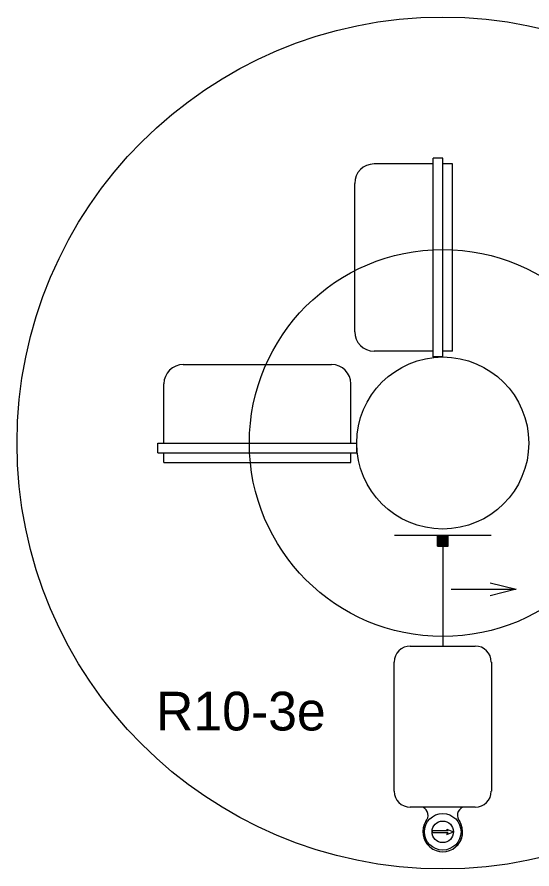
# Model space of a CAD drawing. Extents: x 1695551 to 1695718, y 544410 to 544516.
# Drawn here: x 1695671 to 1695680.98, y 544457.81 to 544474.32 of the extents above; entities that cross this region are included whole.
import ezdxf

# ---------------------------------------------------------------- set-up
doc = ezdxf.new("R2010")
doc.units = 0
doc.layers.add('T_Drafting', color=7, linetype='Continuous')

msp = doc.modelspace()

# ---------------------------------------------------------------- linework, layer by layer
at = {"layer": 'T_Drafting'}
for p, q in [((1695679.065, 544467.733), (1695679.065, 544471.587)), ((1695679.252, 544471.587), (1695679.065, 544471.587)), ((1695679.252, 544467.733), (1695679.252, 544471.587)), ((1695679.065, 544471.473), (1695677.919, 544471.473)), ((1695679.44, 544471.473), (1695679.252, 544471.473)), ((1695679.44, 544467.848), (1695679.44, 544471.473)), ((1695677.544, 544468.223), (1695677.544, 544471.098)), ((1695679.065, 544467.848), (1695677.919, 544467.848)), ((1695679.252, 544467.733), (1695679.065, 544467.733)), ((1695679.44, 544467.848), (1695679.252, 544467.848)), ((1695674.221, 544467.587), (1695677.096, 544467.587)), ((1695673.846, 544466.066), (1695673.846, 544467.212)), ((1695677.471, 544466.066), (1695677.471, 544467.212)), ((1695673.731, 544466.066), (1695677.586, 544466.066)), ((1695673.731, 544465.879), (1695673.731, 544466.066)), ((1695677.586, 544465.879), (1695677.586, 544466.066)), ((1695673.731, 544465.879), (1695677.586, 544465.879)), ((1695673.846, 544465.691), (1695673.846, 544465.879)), ((1695677.471, 544465.691), (1695677.471, 544465.879)), ((1695673.846, 544465.691), (1695677.471, 544465.691)), ((1695680.19, 544464.275), (1695678.315, 544464.275)), ((1695679.148, 544464.066), (1695679.148, 544464.275)), ((1695679.148, 544464.068), (1695679.355, 544464.275)), ((1695679.148, 544464.071), (1695679.351, 544464.275)), ((1695679.148, 544464.075), (1695679.348, 544464.275)), ((1695679.148, 544464.079), (1695679.344, 544464.275)), ((1695679.148, 544464.082), (1695679.341, 544464.275)), ((1695679.148, 544464.086), (1695679.337, 544464.275)), ((1695679.148, 544464.089), (1695679.334, 544464.275)), ((1695679.148, 544464.093), (1695679.33, 544464.275)), ((1695679.148, 544464.096), (1695679.327, 544464.275)), ((1695679.148, 544464.1), (1695679.323, 544464.275)), ((1695679.148, 544464.103), (1695679.319, 544464.275)), ((1695679.148, 544464.107), (1695679.316, 544464.275)), ((1695679.148, 544464.11), (1695679.312, 544464.275)), ((1695679.148, 544464.114), (1695679.309, 544464.275)), ((1695679.148, 544464.117), (1695679.305, 544464.275)), ((1695679.148, 544464.121), (1695679.302, 544464.275)), ((1695679.148, 544464.125), (1695679.298, 544464.275)), ((1695679.148, 544464.128), (1695679.295, 544464.275)), ((1695679.148, 544464.132), (1695679.291, 544464.275)), ((1695679.148, 544464.135), (1695679.288, 544464.275)), ((1695679.148, 544464.139), (1695679.284, 544464.275)), ((1695679.148, 544464.142), (1695679.281, 544464.275)), ((1695679.148, 544464.146), (1695679.277, 544464.275)), ((1695679.148, 544464.149), (1695679.274, 544464.275)), ((1695679.148, 544464.153), (1695679.27, 544464.275)), ((1695679.148, 544464.156), (1695679.266, 544464.275)), ((1695679.148, 544464.16), (1695679.263, 544464.275)), ((1695679.148, 544464.163), (1695679.259, 544464.275)), ((1695679.148, 544464.167), (1695679.256, 544464.275)), ((1695679.148, 544464.17), (1695679.252, 544464.275)), ((1695679.148, 544464.174), (1695679.249, 544464.275)), ((1695679.148, 544464.178), (1695679.245, 544464.275)), ((1695679.148, 544464.181), (1695679.242, 544464.275)), ((1695679.148, 544464.185), (1695679.238, 544464.275)), ((1695679.148, 544464.188), (1695679.235, 544464.275)), ((1695679.148, 544464.192), (1695679.231, 544464.275)), ((1695679.148, 544464.195), (1695679.228, 544464.275)), ((1695679.148, 544464.199), (1695679.224, 544464.275)), ((1695679.148, 544464.202), (1695679.221, 544464.275)), ((1695679.148, 544464.206), (1695679.217, 544464.275)), ((1695679.148, 544464.209), (1695679.213, 544464.275)), ((1695679.148, 544464.213), (1695679.21, 544464.275)), ((1695679.148, 544464.216), (1695679.206, 544464.275)), ((1695679.148, 544464.22), (1695679.203, 544464.275)), ((1695679.148, 544464.224), (1695679.199, 544464.275)), ((1695679.148, 544464.227), (1695679.196, 544464.275)), ((1695679.148, 544464.231), (1695679.192, 544464.275)), ((1695679.148, 544464.234), (1695679.189, 544464.275)), ((1695679.148, 544464.238), (1695679.185, 544464.275)), ((1695679.148, 544464.241), (1695679.182, 544464.275)), ((1695679.148, 544464.245), (1695679.178, 544464.275)), ((1695679.148, 544464.248), (1695679.175, 544464.275)), ((1695679.148, 544464.252), (1695679.171, 544464.275)), ((1695679.148, 544464.255), (1695679.167, 544464.275)), ((1695679.148, 544464.259), (1695679.164, 544464.275)), ((1695679.148, 544464.262), (1695679.16, 544464.275)), ((1695679.148, 544464.266), (1695679.157, 544464.275)), ((1695679.148, 544464.269), (1695679.153, 544464.275)), ((1695679.148, 544464.273), (1695679.15, 544464.275)), ((1695679.15, 544464.066), (1695679.356, 544464.273)), ((1695679.154, 544464.066), (1695679.356, 544464.269)), ((1695679.157, 544464.066), (1695679.356, 544464.266)), ((1695679.356, 544464.066), (1695679.356, 544464.275)), ((1695679.161, 544464.066), (1695679.356, 544464.262)), ((1695679.164, 544464.066), (1695679.356, 544464.259)), ((1695679.168, 544464.066), (1695679.356, 544464.255)), ((1695679.171, 544464.066), (1695679.356, 544464.252)), ((1695679.175, 544464.066), (1695679.356, 544464.248)), ((1695679.178, 544464.066), (1695679.356, 544464.244)), ((1695679.182, 544464.066), (1695679.356, 544464.241)), ((1695679.185, 544464.066), (1695679.356, 544464.237)), ((1695679.189, 544464.066), (1695679.356, 544464.234)), ((1695679.192, 544464.066), (1695679.356, 544464.23)), ((1695679.196, 544464.066), (1695679.356, 544464.227)), ((1695679.2, 544464.066), (1695679.356, 544464.223)), ((1695679.203, 544464.066), (1695679.356, 544464.22)), ((1695679.207, 544464.066), (1695679.356, 544464.216)), ((1695679.21, 544464.066), (1695679.356, 544464.213)), ((1695679.214, 544464.066), (1695679.356, 544464.209)), ((1695679.217, 544464.066), (1695679.356, 544464.206)), ((1695679.221, 544464.066), (1695679.356, 544464.202)), ((1695679.224, 544464.066), (1695679.356, 544464.198)), ((1695679.228, 544464.066), (1695679.356, 544464.195)), ((1695679.231, 544464.066), (1695679.356, 544464.191)), ((1695679.235, 544464.066), (1695679.356, 544464.188)), ((1695679.238, 544464.066), (1695679.356, 544464.184)), ((1695679.242, 544464.066), (1695679.356, 544464.181)), ((1695679.246, 544464.066), (1695679.356, 544464.177)), ((1695679.249, 544464.066), (1695679.356, 544464.174)), ((1695679.253, 544464.066), (1695679.356, 544464.17)), ((1695679.256, 544464.066), (1695679.356, 544464.167)), ((1695679.26, 544464.066), (1695679.356, 544464.163)), ((1695679.263, 544464.066), (1695679.356, 544464.16)), ((1695679.267, 544464.066), (1695679.356, 544464.156)), ((1695679.27, 544464.066), (1695679.356, 544464.153)), ((1695679.274, 544464.066), (1695679.356, 544464.149)), ((1695679.277, 544464.066), (1695679.356, 544464.145)), ((1695679.281, 544464.066), (1695679.356, 544464.142)), ((1695679.284, 544464.066), (1695679.356, 544464.138)), ((1695679.288, 544464.066), (1695679.356, 544464.135)), ((1695679.291, 544464.066), (1695679.356, 544464.131)), ((1695679.295, 544464.066), (1695679.356, 544464.128)), ((1695679.299, 544464.066), (1695679.356, 544464.124)), ((1695679.302, 544464.066), (1695679.356, 544464.121)), ((1695679.306, 544464.066), (1695679.356, 544464.117)), ((1695679.309, 544464.066), (1695679.356, 544464.114)), ((1695679.313, 544464.066), (1695679.356, 544464.11)), ((1695679.316, 544464.066), (1695679.356, 544464.107)), ((1695679.32, 544464.066), (1695679.356, 544464.103)), ((1695679.148, 544464.066), (1695679.356, 544464.066)), ((1695679.252, 544464.066), (1695679.252, 544462.132)), ((1695679.323, 544464.066), (1695679.356, 544464.1)), ((1695679.327, 544464.066), (1695679.356, 544464.096)), ((1695679.33, 544464.066), (1695679.356, 544464.092)), ((1695679.334, 544464.066), (1695679.356, 544464.089)), ((1695679.337, 544464.066), (1695679.356, 544464.085)), ((1695679.341, 544464.066), (1695679.356, 544464.082)), ((1695679.345, 544464.066), (1695679.356, 544464.078)), ((1695679.348, 544464.066), (1695679.356, 544464.075)), ((1695679.352, 544464.066), (1695679.356, 544464.071)), ((1695679.355, 544464.066), (1695679.356, 544464.068)), ((1695679.413, 544463.233), (1695680.672, 544463.233)), ((1695678.623, 544462.132), (1695679.881, 544462.132)), ((1695678.311, 544459.32), (1695678.311, 544461.82)), ((1695680.194, 544461.82), (1695680.194, 544459.32)), ((1695679.881, 544459.007), (1695678.623, 544459.007)), ((1695679.045, 544458.551), (1695679.045, 544458.514)), ((1695679.359, 544458.551), (1695679.045, 544458.551)), ((1695679.359, 544458.514), (1695679.045, 544458.514)), ((1695679.334, 544458.582), (1695679.461, 544458.532)), ((1695679.359, 544458.551), (1695679.334, 544458.582)), ((1695679.334, 544458.482), (1695679.461, 544458.532)), ((1695679.334, 544458.482), (1695679.359, 544458.514))]:
    msp.add_line(p, q, dxfattribs=at)
msp.add_lwpolyline([(1695680.172, 544463.358), (1695680.672, 544463.233), (1695680.172, 544463.108)], dxfattribs=at)
for centre, radius in [((1695679.252, 544466.066), 8.254), ((1695679.252, 544466.066), 3.75), ((1695679.252, 544466.066), 1.667), ((1695679.252, 544458.532), 0.354), ((1695679.252, 544458.532), 0.208)]:
    msp.add_circle(centre, radius, dxfattribs=at)
for centre, radius, start, end in [((1695677.919, 544471.098), 0.375, 90, 180), ((1695677.919, 544468.223), 0.375, 180, 270), ((1695674.221, 544467.212), 0.375, 90, 180), ((1695677.096, 544467.212), 0.375, 360, 90), ((1695678.623, 544461.82), 0.312, 90, 180), ((1695679.881, 544461.82), 0.312, 0, 90), ((1695678.623, 544459.32), 0.312, 180, 270), ((1695679.881, 544459.32), 0.312, 270, 0), ((1695678.792, 544458.849), 0.175, 318.1972, 64.8044), ((1695679.712, 544458.849), 0.175, 115.1956, 221.8028), ((1695679.252, 544458.532), 0.385, 148.7402, 227.4934), ((1695679.252, 544458.532), 0.385, 148.7402, 31.2598), ((1695679.252, 544458.532), 0.385, 312.5066, 31.2598)]:
    msp.add_arc(centre, radius, start, end, dxfattribs=at)

# ---------------------------------------------------------------- texts
msp.add_text('R10-3e', height=0.75, dxfattribs=at).set_placement((1695673.693, 544460.496))

doc.saveas('drawing.dxf')
